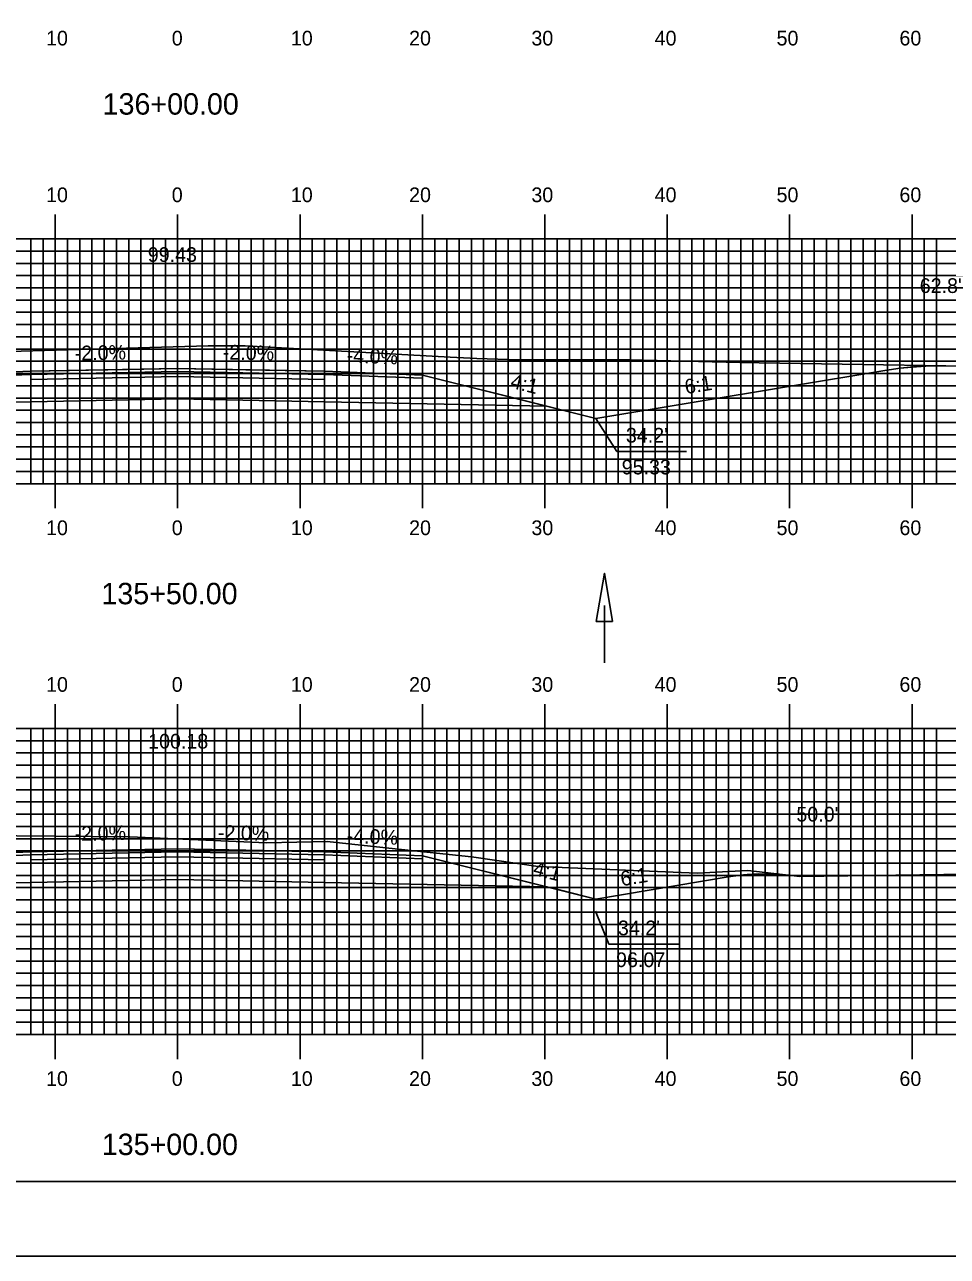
# Model space of a CAD drawing. Extents: x 1775170 to 1775514, y 442591 to 442811.
# Drawn here: x 1775323.7 to 1775399.1, y 442590.5 to 442691.2 of the extents above; entities that cross this region are included whole.
import ezdxf

# ---------------------------------------------------------------- set-up
doc = ezdxf.new("R2010")
doc.units = 0
for name, color, linetype in [('ANNOTATION', 7, 'Continuous'), ('BORDER', 7, 'Continuous'), ('D_Drainage_Ditch_Line', 7, 'Continuous'), ('D_Roadway_Centerline', 7, 'Continuous'), ('D_Roadway_Centerline_Text', 7, 'Continuous'), ('D_Roadway_Edge_Shoulder', 7, 'Continuous'), ('D_Roadway_Edge_TW', 7, 'Continuous'), ('D_Roadway_Pavement', 7, 'Continuous'), ('D_Roadway_SlopeLines', 7, 'Continuous'), ('D_Roadway_SubGrade', 7, 'Continuous'), ('D_Text_Standard', 7, 'Continuous'), ('H_V ANNOTATION', 7, 'Continuous'), ('MAJOR', 7, 'Continuous'), ('MINOR', 7, 'Continuous'), ('PLOT BOUNDARY', 7, 'Continuous'), ('S_Roadway_Centerline', 7, 'Continuous')]:
    doc.layers.add(name, color=color, linetype=linetype)

msp = doc.modelspace()

# ---------------------------------------------------------------- linework, layer by layer
at = {"layer": 'ANNOTATION'}
for points in [[(1775377.78, 442656.3), (1775372.09, 442656.3), (1775370.37, 442658.99)], [(1775377.12, 442616.06), (1775371.43, 442616.06), (1775370.33, 442618.74)]]:
    msp.add_lwpolyline(points, dxfattribs=at)
at = {"layer": 'BORDER'}
msp.add_lwpolyline([(1775186.6, 442596.67), (1775506.6, 442596.67), (1775506.6, 442806.67), (1775186.6, 442806.67)], close=True, dxfattribs=at)
at = {"layer": 'D_Drainage_Ditch_Line'}
msp.add_line((1775371.06, 442643.73), (1775371.06, 442639.03), dxfattribs=at)
msp.add_lwpolyline([(1775370.4, 442642.42), (1775371.72, 442642.42), (1775371.06, 442646.36)], close=True, dxfattribs=at)
at = {"layer": 'D_Roadway_Centerline'}
for points in [[(1775316.2, 442662.53), (1775324.2, 442662.85), (1775332.07, 442663.01), (1775336.2, 442663.09), (1775341.76, 442662.98), (1775348.2, 442662.85), (1775356.2, 442662.53), (1775366.37, 442659.99), (1775367.65, 442659.67), (1775370.37, 442658.99), (1775370.37, 442658.99), (1775393.97, 442662.92), (1775395.22, 442663.1), (1775396.33, 442663.21), (1775396.47, 442663.23), (1775396.57, 442663.23), (1775397.72, 442663.29), (1775398.97, 442663.3)], [(1775316.2, 442623.28), (1775324.2, 442623.6), (1775336.2, 442623.84), (1775347.39, 442623.62), (1775348.2, 442623.6), (1775356.2, 442623.28), (1775366.37, 442620.74), (1775367.5, 442620.46), (1775370.37, 442619.74), (1775381.19, 442621.54), (1775381.19, 442621.54), (1775382.44, 442621.71), (1775382.72, 442621.73), (1775383.69, 442621.79), (1775384.94, 442621.78), (1775386.19, 442621.68)]]:
    msp.add_lwpolyline(points, dxfattribs=at)
at = {"layer": 'D_Roadway_Edge_Shoulder'}
for points in [[(1775324.2, 442662.85), (1775316.2, 442662.53), (1775316.2, 442662.28), (1775324.2, 442662.6)], [(1775348.2, 442662.85), (1775356.2, 442662.53), (1775356.2, 442662.28), (1775348.2, 442662.6)], [(1775324.2, 442623.6), (1775316.2, 442623.28), (1775316.2, 442623.03), (1775324.2, 442623.35)], [(1775348.2, 442623.6), (1775356.2, 442623.28), (1775356.2, 442623.03), (1775348.2, 442623.35)]]:
    msp.add_lwpolyline(points, close=True, dxfattribs=at)
at = {"layer": 'D_Roadway_Edge_TW'}
for points in [[(1775324.2, 442662.6), (1775324.2, 442662.85), (1775336.2, 442663.09), (1775348.2, 442662.85), (1775348.2, 442662.6), (1775336.2, 442662.84)], [(1775324.2, 442623.35), (1775324.2, 442623.6), (1775336.2, 442623.84), (1775348.2, 442623.6), (1775348.2, 442623.35), (1775336.2, 442623.59)]]:
    msp.add_lwpolyline(points, close=True, dxfattribs=at)
at = {"layer": 'D_Roadway_Pavement'}
for points in [[(1775324.2, 442662.19), (1775324.2, 442662.6), (1775336.2, 442662.84), (1775348.2, 442662.6), (1775348.2, 442662.19), (1775336.2, 442662.43)], [(1775324.2, 442622.94), (1775324.2, 442623.35), (1775336.2, 442623.59), (1775348.2, 442623.35), (1775348.2, 442622.94), (1775336.2, 442623.18)]]:
    msp.add_lwpolyline(points, close=True, dxfattribs=at)
at = {"layer": 'D_Roadway_SlopeLines'}
for points in [[(1775356.2, 442662.53), (1775370.37, 442658.99)], [(1775370.37, 442658.99), (1775393.97, 442662.92), (1775395.22, 442663.1), (1775396.47, 442663.23), (1775397.72, 442663.29), (1775398.97, 442663.3)], [(1775356.2, 442623.28), (1775370.37, 442619.74)], [(1775370.37, 442619.74), (1775381.19, 442621.54), (1775382.44, 442621.71), (1775383.69, 442621.79), (1775384.94, 442621.78), (1775386.19, 442621.68)]]:
    msp.add_lwpolyline(points, dxfattribs=at)
at = {"layer": 'D_Roadway_SubGrade'}
for points in [[(1775324.2, 442660.35), (1775306.02, 442659.99), (1775316.2, 442662.53), (1775316.2, 442662.28), (1775324.2, 442662.6), (1775336.2, 442662.84), (1775348.2, 442662.6), (1775356.2, 442662.28), (1775356.2, 442662.53), (1775366.37, 442659.99), (1775348.2, 442660.35), (1775336.2, 442660.59)], [(1775324.2, 442621.1), (1775306.02, 442620.74), (1775316.2, 442623.28), (1775316.2, 442623.03), (1775324.2, 442623.35), (1775336.2, 442623.59), (1775348.2, 442623.35), (1775356.2, 442623.03), (1775356.2, 442623.28), (1775366.37, 442620.74), (1775348.2, 442621.1), (1775336.2, 442621.34)]]:
    msp.add_lwpolyline(points, close=True, dxfattribs=at)
at = {"layer": 'MAJOR'}
for p, q in [((1775326.2, 442675.67), (1775326.2, 442673.67)), ((1775336.2, 442675.67), (1775336.2, 442673.67)), ((1775346.2, 442675.67), (1775346.2, 442673.67)), ((1775356.2, 442675.67), (1775356.2, 442673.67)), ((1775366.2, 442675.67), (1775366.2, 442673.67)), ((1775376.2, 442675.67), (1775376.2, 442673.67)), ((1775386.2, 442675.67), (1775386.2, 442673.67)), ((1775396.2, 442675.67), (1775396.2, 442673.67)), ((1775196.2, 442673.67), (1775476.2, 442673.67)), ((1775196.2, 442673.67), (1775476.2, 442673.67)), ((1775326.2, 442653.67), (1775326.2, 442673.67)), ((1775336.2, 442653.67), (1775336.2, 442673.67)), ((1775346.2, 442653.67), (1775346.2, 442673.67)), ((1775356.2, 442653.67), (1775356.2, 442673.67)), ((1775366.2, 442653.67), (1775366.2, 442673.67)), ((1775376.2, 442653.67), (1775376.2, 442673.67)), ((1775386.2, 442653.67), (1775386.2, 442673.67)), ((1775396.2, 442653.67), (1775396.2, 442673.67)), ((1775196.2, 442668.67), (1775476.2, 442668.67)), ((1775196.2, 442663.67), (1775476.2, 442663.67)), ((1775196.2, 442658.67), (1775476.2, 442658.67)), ((1775196.2, 442653.67), (1775476.2, 442653.67)), ((1775196.2, 442653.67), (1775476.2, 442653.67)), ((1775326.2, 442651.66), (1775326.2, 442653.67)), ((1775336.2, 442651.66), (1775336.2, 442653.67)), ((1775346.2, 442651.66), (1775346.2, 442653.67)), ((1775356.2, 442651.66), (1775356.2, 442653.67)), ((1775366.2, 442651.66), (1775366.2, 442653.67)), ((1775376.2, 442651.66), (1775376.2, 442653.67)), ((1775386.2, 442651.66), (1775386.2, 442653.67)), ((1775396.2, 442651.66), (1775396.2, 442653.67)), ((1775326.2, 442635.67), (1775326.2, 442633.67)), ((1775336.2, 442635.67), (1775336.2, 442633.67)), ((1775346.2, 442635.67), (1775346.2, 442633.67)), ((1775356.2, 442635.67), (1775356.2, 442633.67)), ((1775366.2, 442635.67), (1775366.2, 442633.67)), ((1775376.2, 442635.67), (1775376.2, 442633.67)), ((1775386.2, 442635.67), (1775386.2, 442633.67)), ((1775396.2, 442635.67), (1775396.2, 442633.67)), ((1775196.2, 442633.67), (1775476.2, 442633.67)), ((1775196.2, 442633.67), (1775476.2, 442633.67)), ((1775326.2, 442608.67), (1775326.2, 442633.67)), ((1775336.2, 442608.67), (1775336.2, 442633.67)), ((1775346.2, 442608.67), (1775346.2, 442633.67)), ((1775356.2, 442608.67), (1775356.2, 442633.67)), ((1775366.2, 442608.67), (1775366.2, 442633.67)), ((1775376.2, 442608.67), (1775376.2, 442633.67)), ((1775386.2, 442608.67), (1775386.2, 442633.67)), ((1775396.2, 442608.67), (1775396.2, 442633.67)), ((1775196.2, 442628.67), (1775476.2, 442628.67)), ((1775196.2, 442623.67), (1775476.2, 442623.67)), ((1775196.2, 442618.67), (1775476.2, 442618.67)), ((1775196.2, 442613.67), (1775476.2, 442613.67)), ((1775196.2, 442608.67), (1775476.2, 442608.67)), ((1775196.2, 442608.67), (1775476.2, 442608.67)), ((1775326.2, 442606.66), (1775326.2, 442608.67)), ((1775336.2, 442606.66), (1775336.2, 442608.67)), ((1775346.2, 442606.66), (1775346.2, 442608.67)), ((1775356.2, 442606.66), (1775356.2, 442608.67)), ((1775366.2, 442606.66), (1775366.2, 442608.67)), ((1775376.2, 442606.66), (1775376.2, 442608.67)), ((1775386.2, 442606.66), (1775386.2, 442608.67)), ((1775396.2, 442606.66), (1775396.2, 442608.67))]:
    msp.add_line(p, q, dxfattribs=at)
at = {"layer": 'MINOR'}
for p, q in [((1775324.2, 442653.67), (1775324.2, 442673.67)), ((1775325.2, 442653.67), (1775325.2, 442673.67)), ((1775327.2, 442653.67), (1775327.2, 442673.67)), ((1775328.2, 442653.67), (1775328.2, 442673.67)), ((1775329.2, 442653.67), (1775329.2, 442673.67)), ((1775330.2, 442653.67), (1775330.2, 442673.67)), ((1775331.2, 442653.67), (1775331.2, 442673.67)), ((1775332.2, 442653.67), (1775332.2, 442673.67)), ((1775333.2, 442653.67), (1775333.2, 442673.67)), ((1775334.2, 442653.67), (1775334.2, 442673.67)), ((1775335.2, 442653.67), (1775335.2, 442673.67)), ((1775337.2, 442653.67), (1775337.2, 442673.67)), ((1775338.2, 442653.67), (1775338.2, 442673.67)), ((1775339.2, 442653.67), (1775339.2, 442673.67)), ((1775340.2, 442653.67), (1775340.2, 442673.67)), ((1775341.2, 442653.67), (1775341.2, 442673.67)), ((1775342.2, 442653.67), (1775342.2, 442673.67)), ((1775343.2, 442653.67), (1775343.2, 442673.67)), ((1775344.2, 442653.67), (1775344.2, 442673.67)), ((1775345.2, 442653.67), (1775345.2, 442673.67)), ((1775347.2, 442653.67), (1775347.2, 442673.67)), ((1775348.2, 442653.67), (1775348.2, 442673.67)), ((1775349.2, 442653.67), (1775349.2, 442673.67)), ((1775350.2, 442653.67), (1775350.2, 442673.67)), ((1775351.2, 442653.67), (1775351.2, 442673.67)), ((1775352.2, 442653.67), (1775352.2, 442673.67)), ((1775353.2, 442653.67), (1775353.2, 442673.67)), ((1775354.2, 442653.67), (1775354.2, 442673.67)), ((1775355.2, 442653.67), (1775355.2, 442673.67)), ((1775357.2, 442653.67), (1775357.2, 442673.67)), ((1775358.2, 442653.67), (1775358.2, 442673.67)), ((1775359.2, 442653.67), (1775359.2, 442673.67)), ((1775360.2, 442653.67), (1775360.2, 442673.67)), ((1775361.2, 442653.67), (1775361.2, 442673.67)), ((1775362.2, 442653.67), (1775362.2, 442673.67)), ((1775363.2, 442653.67), (1775363.2, 442673.67)), ((1775364.2, 442653.67), (1775364.2, 442673.67)), ((1775365.2, 442653.67), (1775365.2, 442673.67)), ((1775367.2, 442653.67), (1775367.2, 442673.67)), ((1775368.2, 442653.67), (1775368.2, 442673.67)), ((1775369.2, 442653.67), (1775369.2, 442673.67)), ((1775370.2, 442653.67), (1775370.2, 442673.67)), ((1775371.2, 442653.67), (1775371.2, 442673.67)), ((1775372.2, 442653.67), (1775372.2, 442673.67)), ((1775373.2, 442653.67), (1775373.2, 442673.67)), ((1775374.2, 442653.67), (1775374.2, 442673.67)), ((1775375.2, 442653.67), (1775375.2, 442673.67)), ((1775377.2, 442653.67), (1775377.2, 442673.67)), ((1775378.2, 442653.67), (1775378.2, 442673.67)), ((1775379.2, 442653.67), (1775379.2, 442673.67)), ((1775380.2, 442653.67), (1775380.2, 442673.67)), ((1775381.2, 442653.67), (1775381.2, 442673.67)), ((1775382.2, 442653.67), (1775382.2, 442673.67)), ((1775383.2, 442653.67), (1775383.2, 442673.67)), ((1775384.2, 442653.67), (1775384.2, 442673.67)), ((1775385.2, 442653.67), (1775385.2, 442673.67)), ((1775387.2, 442653.67), (1775387.2, 442673.67)), ((1775388.2, 442653.67), (1775388.2, 442673.67)), ((1775389.2, 442653.67), (1775389.2, 442673.67)), ((1775390.2, 442653.67), (1775390.2, 442673.67)), ((1775391.2, 442653.67), (1775391.2, 442673.67)), ((1775392.2, 442653.67), (1775392.2, 442673.67)), ((1775393.2, 442653.67), (1775393.2, 442673.67)), ((1775394.2, 442653.67), (1775394.2, 442673.67)), ((1775395.2, 442653.67), (1775395.2, 442673.67)), ((1775397.2, 442653.67), (1775397.2, 442673.67)), ((1775398.2, 442653.67), (1775398.2, 442673.67)), ((1775196.2, 442672.67), (1775476.2, 442672.67)), ((1775196.2, 442671.67), (1775476.2, 442671.67)), ((1775196.2, 442670.67), (1775476.2, 442670.67)), ((1775196.2, 442669.67), (1775476.2, 442669.67)), ((1775196.2, 442667.67), (1775476.2, 442667.67)), ((1775196.2, 442666.67), (1775476.2, 442666.67)), ((1775196.2, 442665.67), (1775476.2, 442665.67)), ((1775196.2, 442664.67), (1775476.2, 442664.67)), ((1775196.2, 442662.67), (1775476.2, 442662.67)), ((1775196.2, 442661.67), (1775476.2, 442661.67)), ((1775196.2, 442660.67), (1775476.2, 442660.67)), ((1775196.2, 442659.67), (1775476.2, 442659.67)), ((1775196.2, 442657.67), (1775476.2, 442657.67)), ((1775196.2, 442656.67), (1775476.2, 442656.67)), ((1775196.2, 442655.67), (1775476.2, 442655.67)), ((1775196.2, 442654.67), (1775476.2, 442654.67)), ((1775324.2, 442608.67), (1775324.2, 442633.67)), ((1775325.2, 442608.67), (1775325.2, 442633.67)), ((1775327.2, 442608.67), (1775327.2, 442633.67)), ((1775328.2, 442608.67), (1775328.2, 442633.67)), ((1775329.2, 442608.67), (1775329.2, 442633.67)), ((1775330.2, 442608.67), (1775330.2, 442633.67)), ((1775331.2, 442608.67), (1775331.2, 442633.67)), ((1775332.2, 442608.67), (1775332.2, 442633.67)), ((1775333.2, 442608.67), (1775333.2, 442633.67)), ((1775334.2, 442608.67), (1775334.2, 442633.67)), ((1775335.2, 442608.67), (1775335.2, 442633.67)), ((1775337.2, 442608.67), (1775337.2, 442633.67)), ((1775338.2, 442608.67), (1775338.2, 442633.67)), ((1775339.2, 442608.67), (1775339.2, 442633.67)), ((1775340.2, 442608.67), (1775340.2, 442633.67)), ((1775341.2, 442608.67), (1775341.2, 442633.67)), ((1775342.2, 442608.67), (1775342.2, 442633.67)), ((1775343.2, 442608.67), (1775343.2, 442633.67)), ((1775344.2, 442608.67), (1775344.2, 442633.67)), ((1775345.2, 442608.67), (1775345.2, 442633.67)), ((1775347.2, 442608.67), (1775347.2, 442633.67)), ((1775348.2, 442608.67), (1775348.2, 442633.67)), ((1775349.2, 442608.67), (1775349.2, 442633.67)), ((1775350.2, 442608.67), (1775350.2, 442633.67)), ((1775351.2, 442608.67), (1775351.2, 442633.67)), ((1775352.2, 442608.67), (1775352.2, 442633.67)), ((1775353.2, 442608.67), (1775353.2, 442633.67)), ((1775354.2, 442608.67), (1775354.2, 442633.67)), ((1775355.2, 442608.67), (1775355.2, 442633.67)), ((1775357.2, 442608.67), (1775357.2, 442633.67)), ((1775358.2, 442608.67), (1775358.2, 442633.67)), ((1775359.2, 442608.67), (1775359.2, 442633.67)), ((1775360.2, 442608.67), (1775360.2, 442633.67)), ((1775361.2, 442608.67), (1775361.2, 442633.67)), ((1775362.2, 442608.67), (1775362.2, 442633.67)), ((1775363.2, 442608.67), (1775363.2, 442633.67)), ((1775364.2, 442608.67), (1775364.2, 442633.67)), ((1775365.2, 442608.67), (1775365.2, 442633.67)), ((1775367.2, 442608.67), (1775367.2, 442633.67)), ((1775368.2, 442608.67), (1775368.2, 442633.67)), ((1775369.2, 442608.67), (1775369.2, 442633.67)), ((1775370.2, 442608.67), (1775370.2, 442633.67)), ((1775371.2, 442608.67), (1775371.2, 442633.67)), ((1775372.2, 442608.67), (1775372.2, 442633.67)), ((1775373.2, 442608.67), (1775373.2, 442633.67)), ((1775374.2, 442608.67), (1775374.2, 442633.67)), ((1775375.2, 442608.67), (1775375.2, 442633.67)), ((1775377.2, 442608.67), (1775377.2, 442633.67)), ((1775378.2, 442608.67), (1775378.2, 442633.67)), ((1775379.2, 442608.67), (1775379.2, 442633.67)), ((1775380.2, 442608.67), (1775380.2, 442633.67)), ((1775381.2, 442608.67), (1775381.2, 442633.67)), ((1775382.2, 442608.67), (1775382.2, 442633.67)), ((1775383.2, 442608.67), (1775383.2, 442633.67)), ((1775384.2, 442608.67), (1775384.2, 442633.67)), ((1775385.2, 442608.67), (1775385.2, 442633.67)), ((1775387.2, 442608.67), (1775387.2, 442633.67)), ((1775388.2, 442608.67), (1775388.2, 442633.67)), ((1775389.2, 442608.67), (1775389.2, 442633.67)), ((1775390.2, 442608.67), (1775390.2, 442633.67)), ((1775391.2, 442608.67), (1775391.2, 442633.67)), ((1775392.2, 442608.67), (1775392.2, 442633.67)), ((1775393.2, 442608.67), (1775393.2, 442633.67)), ((1775394.2, 442608.67), (1775394.2, 442633.67)), ((1775395.2, 442608.67), (1775395.2, 442633.67)), ((1775397.2, 442608.67), (1775397.2, 442633.67)), ((1775398.2, 442608.67), (1775398.2, 442633.67)), ((1775196.2, 442632.67), (1775476.2, 442632.67)), ((1775196.2, 442631.67), (1775476.2, 442631.67)), ((1775196.2, 442630.67), (1775476.2, 442630.67)), ((1775196.2, 442629.67), (1775476.2, 442629.67)), ((1775196.2, 442627.67), (1775476.2, 442627.67)), ((1775196.2, 442626.67), (1775476.2, 442626.67)), ((1775196.2, 442625.67), (1775476.2, 442625.67)), ((1775196.2, 442624.67), (1775476.2, 442624.67)), ((1775196.2, 442622.67), (1775476.2, 442622.67)), ((1775196.2, 442621.67), (1775476.2, 442621.67)), ((1775196.2, 442620.67), (1775476.2, 442620.67)), ((1775196.2, 442619.67), (1775476.2, 442619.67)), ((1775196.2, 442617.67), (1775476.2, 442617.67)), ((1775196.2, 442616.67), (1775476.2, 442616.67)), ((1775196.2, 442615.67), (1775476.2, 442615.67)), ((1775196.2, 442614.67), (1775476.2, 442614.67)), ((1775196.2, 442612.67), (1775476.2, 442612.67)), ((1775196.2, 442611.67), (1775476.2, 442611.67)), ((1775196.2, 442610.67), (1775476.2, 442610.67)), ((1775196.2, 442609.67), (1775476.2, 442609.67))]:
    msp.add_line(p, q, dxfattribs=at)
at = {"layer": 'PLOT BOUNDARY'}
msp.add_lwpolyline([(1775170.41, 442590.55), (1775510.41, 442590.55), (1775510.41, 442810.55), (1775170.41, 442810.55)], close=True, dxfattribs=at)
at = {"layer": 'S_Roadway_Centerline'}
for points in [[(1775250, 442664.76), (1775263.15, 442664.96), (1775272.62, 442664.63), (1775287.79, 442664.69), (1775291.22, 442664.83), (1775294.81, 442664.71), (1775311.18, 442664.42), (1775314.48, 442664.34), (1775317.68, 442664.33), (1775338.68, 442664.93), (1775341.71, 442664.94), (1775358.47, 442664.01), (1775360.64, 442663.9), (1775363.21, 442663.82), (1775373.11, 442663.8), (1775382.13, 442663.57), (1775383.72, 442663.54), (1775407.44, 442663.17)], [(1775261.35, 442625.63), (1775275.14, 442625.51), (1775282.45, 442625.59), (1775298.39, 442625.03), (1775307.55, 442624.86), (1775313.47, 442624.9), (1775319.95, 442624.93), (1775332.28, 442624.82), (1775343.45, 442624.33), (1775348.41, 442624.44), (1775353.96, 442623.83), (1775360.21, 442623.19), (1775365.65, 442622.41), (1775378.64, 442621.86), (1775382.79, 442622.06), (1775387.02, 442621.59), (1775400.77, 442621.77)]]:
    msp.add_lwpolyline(points, dxfattribs=at)

# ---------------------------------------------------------------- texts
at = {"layer": 'ANNOTATION'}
for s, rotation, p in [('-2.0%', 1.1458, (1775327.8, 442663.73)), ('-2.0%', 358.8542, (1775339.88, 442663.82)), ('-4.0%', 357.7095, (1775349.99, 442663.58)), ('4:1', 345.9618, (1775363.32, 442661.52)), ('6:1', 9.4616, (1775377.73, 442660.98)), ('-2.0%', 1.1457, (1775327.8, 442624.48)), ('-2.0%', 358.8542, (1775339.48, 442624.58)), ('-4.0%', 357.7095, (1775349.99, 442624.33)), ('4:1', 345.9599, (1775365.17, 442621.72)), ('6:1', 9.4603, (1775372.48, 442620.78))]:
    msp.add_text(s, height=1.2, rotation=rotation, dxfattribs=at).set_placement(p)
for s, p in [("34.2'", (1775372.82, 442657.03)), ('95.33', (1775372.48, 442654.43)), ("34.2'", (1775372.17, 442616.78)), ('96.07', (1775372.02, 442614.18))]:
    msp.add_text(s, height=1.2, dxfattribs=at).set_placement(p)
at = {"layer": 'D_Roadway_Centerline'}
for s, p in [('C', (1775336.19, 442663.09)), ('L', (1775336.2, 442663.09)), ('C', (1775336.19, 442623.84)), ('L', (1775336.2, 442623.84))]:
    msp.add_text(s, height=0.0146, dxfattribs=at).set_placement(p)
at = {"layer": 'D_Roadway_Centerline_Text'}
for s, p in [('99.43', (1775333.76, 442671.79)), ('100.18', (1775333.79, 442632.03))]:
    msp.add_text(s, height=1.2, dxfattribs=at).set_placement(p)
at = {"layer": 'D_Text_Standard'}
for s, p in [("62.8'", (1775396.83, 442669.25)), ("50.0'", (1775386.75, 442626.07))]:
    msp.add_text(s, height=1.2, dxfattribs=at).set_placement(p)
at = {"layer": 'H_V ANNOTATION'}
for s, height, p in [('10', 1.2, (1775325.45, 442689.47)), ('0', 1.2, (1775335.72, 442689.47)), ('10', 1.2, (1775345.45, 442689.47)), ('20', 1.2, (1775355.11, 442689.47)), ('30', 1.2, (1775365.1, 442689.47)), ('40', 1.2, (1775375.17, 442689.47)), ('50', 1.2, (1775385.13, 442689.47)), ('60', 1.2, (1775395.17, 442689.47)), ('136+00.00', 1.75, (1775330.07, 442683.82)), ('10', 1.2, (1775325.45, 442676.67)), ('0', 1.2, (1775335.72, 442676.67)), ('10', 1.2, (1775345.45, 442676.67)), ('20', 1.2, (1775355.11, 442676.67)), ('30', 1.2, (1775365.1, 442676.67)), ('40', 1.2, (1775375.17, 442676.67)), ('50', 1.2, (1775385.13, 442676.67)), ('60', 1.2, (1775395.17, 442676.67)), ('10', 1.2, (1775325.45, 442649.47)), ('0', 1.2, (1775335.72, 442649.47)), ('10', 1.2, (1775345.45, 442649.47)), ('20', 1.2, (1775355.11, 442649.47)), ('30', 1.2, (1775365.1, 442649.47)), ('40', 1.2, (1775375.17, 442649.47)), ('50', 1.2, (1775385.13, 442649.47)), ('60', 1.2, (1775395.17, 442649.47)), ('135+50.00', 1.75, (1775329.97, 442643.82)), ('10', 1.2, (1775325.45, 442636.67)), ('0', 1.2, (1775335.72, 442636.67)), ('10', 1.2, (1775345.45, 442636.67)), ('20', 1.2, (1775355.11, 442636.67)), ('30', 1.2, (1775365.1, 442636.67)), ('40', 1.2, (1775375.17, 442636.67)), ('50', 1.2, (1775385.13, 442636.67)), ('60', 1.2, (1775395.17, 442636.67)), ('10', 1.2, (1775325.45, 442604.47)), ('0', 1.2, (1775335.72, 442604.47)), ('10', 1.2, (1775345.45, 442604.47)), ('20', 1.2, (1775355.11, 442604.47)), ('30', 1.2, (1775365.1, 442604.47)), ('40', 1.2, (1775375.17, 442604.47)), ('50', 1.2, (1775385.13, 442604.47)), ('60', 1.2, (1775395.17, 442604.47)), ('135+00.00', 1.75, (1775330, 442598.82))]:
    msp.add_text(s, height=height, dxfattribs=at).set_placement(p)

doc.saveas('drawing.dxf')
